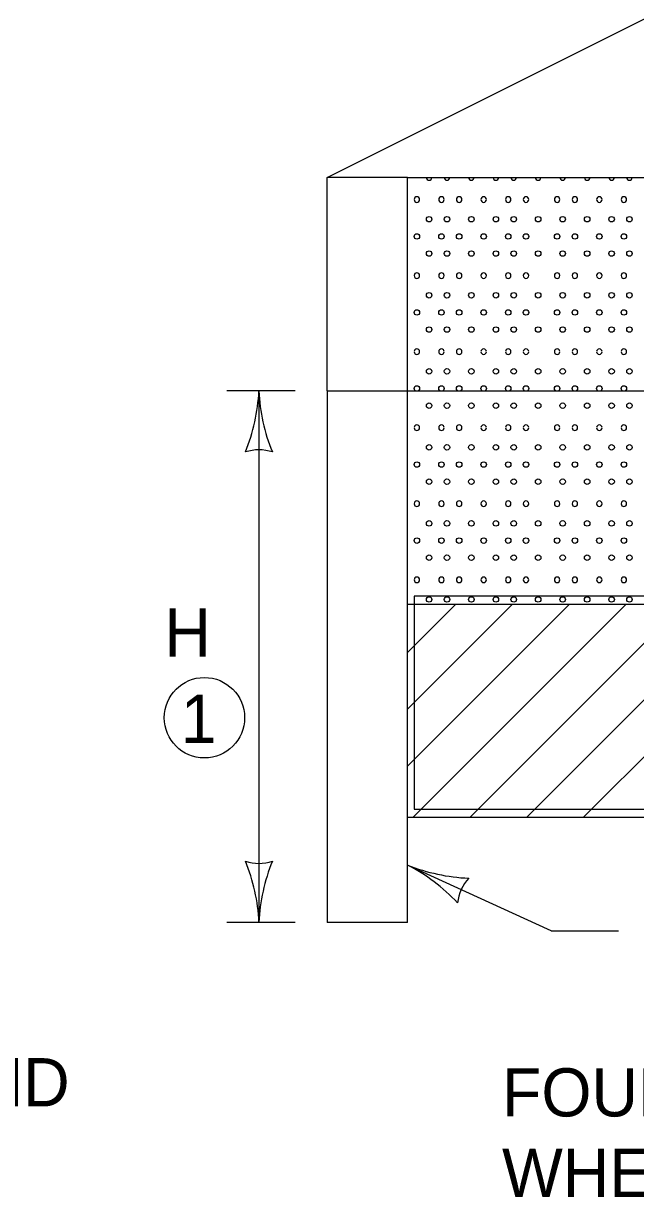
# Model space of a CAD drawing. Extents: x 49991.4 to 50021, y 49987.6 to 50011.4.
# Drawn here: x 50016.641 to 50017.403, y 50005.816 to 50007.277 of the extents above; entities that cross this region are included whole.
import ezdxf

# ---------------------------------------------------------------- set-up
doc = ezdxf.new("R2010")
doc.units = 0
for name, color, linetype in [('Level 1', 7, 'Continuous'), ('Level 2', 7, 'Continuous'), ('Level 3', 7, 'Continuous')]:
    doc.layers.add(name, color=color, linetype=linetype)

msp = doc.modelspace()

# ---------------------------------------------------------------- linework, layer by layer
at = {"layer": 'Level 1'}
for p, q in [((50017.0193, 50007.085), (50018.0803, 50007.6155)), ((50017.0193, 50006.8198), (50017.0193, 50007.085)), ((50017.1193, 50007.085), (50017.0193, 50007.085)), ((50017.1193, 50007.085), (50020.4675, 50007.085)), ((50017.1193, 50006.5545), (50017.1193, 50007.085)), ((50017.0193, 50006.8198), (50020.4675, 50006.8198)), ((50017.0193, 50006.8198), (50017.0193, 50006.1585)), ((50017.1193, 50006.5545), (50020.4675, 50006.5545)), ((50017.1193, 50006.1585), (50017.1193, 50006.5545)), ((50017.1193, 50006.4944), (50017.1794, 50006.5545)), ((50017.1193, 50006.4237), (50017.2501, 50006.5545)), ((50017.1193, 50006.353), (50017.3209, 50006.5545)), ((50017.1264, 50006.2893), (50017.3916, 50006.5545)), ((50020.4675, 50006.5645), (50017.1276, 50006.5644)), ((50017.1276, 50006.5644), (50017.1276, 50006.2993)), ((50017.1971, 50006.2893), (50017.4623, 50006.5545)), ((50017.2678, 50006.2893), (50017.533, 50006.5545)), ((50017.3385, 50006.2893), (50017.6037, 50006.5545)), ((50017.1193, 50006.2893), (50020.4675, 50006.2893)), ((50017.1276, 50006.2993), (50020.4675, 50006.2993)), ((50017.1193, 50006.1585), (50017.0193, 50006.1585))]:
    msp.add_line(p, q, dxfattribs=at)
for centre in [(50017.1462, 50007.0332), (50017.1684, 50007.0332), (50017.1988, 50007.0332), (50017.2293, 50007.0332), (50017.2515, 50007.0332), (50017.2819, 50007.0332), (50017.3124, 50007.0332), (50017.3429, 50007.0332), (50017.3733, 50007.0332), (50017.3955, 50007.0332), (50017.131, 50007.0118), (50017.131, 50007.0118), (50017.1615, 50007.0118), (50017.1836, 50007.0118), (50017.2141, 50007.0118), (50017.2141, 50007.0118), (50017.2446, 50007.0118), (50017.2667, 50007.0118), (50017.3055, 50007.0118), (50017.3276, 50007.0118), (50017.3581, 50007.0118), (50017.3581, 50007.0118), (50017.3886, 50007.0118), (50017.1462, 50006.9905), (50017.1684, 50006.9905), (50017.1988, 50006.9905), (50017.2293, 50006.9905), (50017.2515, 50006.9905), (50017.2819, 50006.9905), (50017.3124, 50006.9905), (50017.3429, 50006.9905), (50017.3733, 50006.9905), (50017.3955, 50006.9905), (50017.1462, 50006.9386), (50017.1684, 50006.9386), (50017.1988, 50006.9386), (50017.2293, 50006.9386), (50017.2515, 50006.9386), (50017.2819, 50006.9386), (50017.3124, 50006.9386), (50017.3429, 50006.9386), (50017.3733, 50006.9386), (50017.3955, 50006.9386), (50017.131, 50006.9172), (50017.131, 50006.9172), (50017.1615, 50006.9172), (50017.1836, 50006.9172), (50017.2141, 50006.9172), (50017.2141, 50006.9172), (50017.2446, 50006.9172), (50017.2667, 50006.9172), (50017.3055, 50006.9172), (50017.3276, 50006.9172), (50017.3581, 50006.9172), (50017.3581, 50006.9172), (50017.3886, 50006.9172), (50017.1462, 50006.8959), (50017.1684, 50006.8959), (50017.1988, 50006.8959), (50017.2293, 50006.8959), (50017.2515, 50006.8959), (50017.2819, 50006.8959), (50017.3124, 50006.8959), (50017.3429, 50006.8959), (50017.3733, 50006.8959), (50017.3955, 50006.8959), (50017.1462, 50006.844), (50017.1684, 50006.844), (50017.1988, 50006.844), (50017.2293, 50006.844), (50017.2515, 50006.844), (50017.2819, 50006.844), (50017.3124, 50006.844), (50017.3429, 50006.844), (50017.3733, 50006.844), (50017.3955, 50006.844), (50017.131, 50006.8226), (50017.131, 50006.8226), (50017.1615, 50006.8226), (50017.1836, 50006.8226), (50017.2141, 50006.8226), (50017.2141, 50006.8226), (50017.2446, 50006.8226), (50017.2667, 50006.8226), (50017.3055, 50006.8226), (50017.3276, 50006.8226), (50017.3581, 50006.8226), (50017.3581, 50006.8226), (50017.3886, 50006.8226), (50017.1462, 50006.8013), (50017.1684, 50006.8013), (50017.1988, 50006.8013), (50017.2293, 50006.8013), (50017.2515, 50006.8013), (50017.2819, 50006.8013), (50017.3124, 50006.8013), (50017.3429, 50006.8013), (50017.3733, 50006.8013), (50017.3955, 50006.8013), (50017.1462, 50006.7494), (50017.1684, 50006.7494), (50017.1988, 50006.7494), (50017.2293, 50006.7494), (50017.2515, 50006.7494), (50017.2819, 50006.7494), (50017.3124, 50006.7494), (50017.3429, 50006.7494), (50017.3733, 50006.7494), (50017.3955, 50006.7494), (50017.131, 50006.728), (50017.131, 50006.728), (50017.1615, 50006.728), (50017.1836, 50006.728), (50017.2141, 50006.728), (50017.2141, 50006.728), (50017.2446, 50006.728), (50017.2667, 50006.728), (50017.3055, 50006.728), (50017.3276, 50006.728), (50017.3581, 50006.728), (50017.3581, 50006.728), (50017.3886, 50006.728), (50017.1462, 50006.7067), (50017.1684, 50006.7067), (50017.1988, 50006.7067), (50017.2293, 50006.7067), (50017.2515, 50006.7067), (50017.2819, 50006.7067), (50017.3124, 50006.7067), (50017.3429, 50006.7067), (50017.3733, 50006.7067), (50017.3955, 50006.7067), (50017.1462, 50006.6548), (50017.1684, 50006.6548), (50017.1988, 50006.6548), (50017.2293, 50006.6548), (50017.2515, 50006.6548), (50017.2819, 50006.6548), (50017.3124, 50006.6548), (50017.3429, 50006.6548), (50017.3733, 50006.6548), (50017.3955, 50006.6548), (50017.131, 50006.6334), (50017.131, 50006.6334), (50017.1615, 50006.6334), (50017.1836, 50006.6334), (50017.2141, 50006.6334), (50017.2141, 50006.6334), (50017.2446, 50006.6334), (50017.2667, 50006.6334), (50017.3055, 50006.6334), (50017.3276, 50006.6334), (50017.3581, 50006.6334), (50017.3581, 50006.6334), (50017.3886, 50006.6334), (50017.1462, 50006.6121), (50017.1684, 50006.6121), (50017.1988, 50006.6121), (50017.2293, 50006.6121), (50017.2515, 50006.6121), (50017.2819, 50006.6121), (50017.3124, 50006.6121), (50017.3429, 50006.6121), (50017.3733, 50006.6121), (50017.3955, 50006.6121), (50017.1462, 50006.5602), (50017.1684, 50006.5602), (50017.1988, 50006.5602), (50017.2293, 50006.5602), (50017.2515, 50006.5602), (50017.2819, 50006.5602), (50017.3124, 50006.5602), (50017.3429, 50006.5602), (50017.3733, 50006.5602), (50017.3955, 50006.5602)]:
    msp.add_circle(centre, 0.00341, dxfattribs=at)
for centre, start, end in [((50017.1462, 50007.0851), 181.8336, 358.1664), ((50017.1684, 50007.0851), 181.8336, 358.1664), ((50017.1988, 50007.0851), 181.8336, 358.1664), ((50017.2293, 50007.0851), 181.8336, 358.1664), ((50017.2515, 50007.0851), 181.8336, 358.1664), ((50017.2819, 50007.0851), 181.8336, 358.1664), ((50017.3124, 50007.0851), 181.8336, 358.1664), ((50017.3429, 50007.0851), 181.8336, 358.1664), ((50017.3733, 50007.0851), 181.8336, 358.1664), ((50017.3955, 50007.0851), 181.8336, 358.1664), ((50017.131, 50007.0577), 0, 180), ((50017.131, 50007.0576), 180, 0), ((50017.131, 50007.0576), 180, 0), ((50017.1615, 50007.0577), 0, 180), ((50017.1615, 50007.0576), 180, 0), ((50017.1836, 50007.0577), 0, 180), ((50017.1836, 50007.0576), 180, 0), ((50017.2141, 50007.0577), 0, 180), ((50017.2141, 50007.0576), 180, 0), ((50017.2141, 50007.0576), 180, 0), ((50017.2446, 50007.0577), 0, 180), ((50017.2446, 50007.0576), 180, 0), ((50017.2667, 50007.0577), 0, 180), ((50017.2667, 50007.0576), 180, 0), ((50017.3055, 50007.0577), 0, 180), ((50017.3055, 50007.0576), 180, 0), ((50017.3276, 50007.0577), 0, 180), ((50017.3276, 50007.0576), 180, 0), ((50017.3581, 50007.0577), 0, 180), ((50017.3581, 50007.0576), 180, 0), ((50017.3581, 50007.0576), 180, 0), ((50017.3886, 50007.0577), 0, 180), ((50017.3886, 50007.0576), 180, 0), ((50017.131, 50006.9631), 0, 180), ((50017.131, 50006.963), 180, 0), ((50017.131, 50006.963), 180, 0), ((50017.1615, 50006.9631), 0, 180), ((50017.1615, 50006.963), 180, 0), ((50017.1836, 50006.9631), 0, 180), ((50017.1836, 50006.963), 180, 0), ((50017.2141, 50006.9631), 0, 180), ((50017.2141, 50006.963), 180, 0), ((50017.2446, 50006.9631), 0, 180), ((50017.2446, 50006.963), 180, 0), ((50017.2667, 50006.9631), 0, 180), ((50017.2667, 50006.963), 180, 0), ((50017.3055, 50006.9631), 0, 180), ((50017.3055, 50006.963), 180, 0), ((50017.3276, 50006.9631), 0, 180), ((50017.3276, 50006.963), 180, 0), ((50017.3581, 50006.9631), 0, 180), ((50017.3581, 50006.963), 180, 0), ((50017.3581, 50006.963), 180, 0), ((50017.3886, 50006.9631), 0, 180), ((50017.3886, 50006.963), 180, 0), ((50017.131, 50006.8685), 0, 180), ((50017.1615, 50006.8685), 0, 180), ((50017.1836, 50006.8685), 0, 180), ((50017.2141, 50006.8685), 0, 180), ((50017.2446, 50006.8685), 0, 180), ((50017.2667, 50006.8685), 0, 180), ((50017.3055, 50006.8685), 0, 180), ((50017.3276, 50006.8685), 0, 180), ((50017.3581, 50006.8685), 0, 180), ((50017.3886, 50006.8685), 0, 180), ((50017.131, 50006.8684), 180, 0), ((50017.131, 50006.8684), 180, 0), ((50017.1615, 50006.8684), 180, 0), ((50017.1836, 50006.8684), 180, 0), ((50017.2141, 50006.8684), 180, 0), ((50017.2141, 50006.8684), 180, 0), ((50017.2446, 50006.8684), 180, 0), ((50017.2667, 50006.8684), 180, 0), ((50017.3055, 50006.8684), 180, 0), ((50017.3276, 50006.8684), 180, 0), ((50017.3581, 50006.8684), 180, 0), ((50017.3581, 50006.8684), 180, 0), ((50017.3886, 50006.8684), 180, 0), ((50017.131, 50006.7739), 0, 180), ((50017.131, 50006.7738), 180, 0), ((50017.131, 50006.7738), 180, 0), ((50017.1615, 50006.7739), 0, 180), ((50017.1615, 50006.7738), 180, 0), ((50017.1836, 50006.7739), 0, 180), ((50017.1836, 50006.7738), 180, 0), ((50017.2141, 50006.7739), 0, 180), ((50017.2141, 50006.7738), 180, 0), ((50017.2141, 50006.7738), 180, 0), ((50017.2446, 50006.7739), 0, 180), ((50017.2446, 50006.7738), 180, 0), ((50017.2667, 50006.7739), 0, 180), ((50017.2667, 50006.7738), 180, 0), ((50017.3055, 50006.7739), 0, 180), ((50017.3055, 50006.7738), 180, 0), ((50017.3276, 50006.7739), 0, 180), ((50017.3276, 50006.7738), 180, 0), ((50017.3581, 50006.7739), 0, 180), ((50017.3581, 50006.7738), 180, 0), ((50017.3581, 50006.7738), 180, 0), ((50017.3886, 50006.7739), 0, 180), ((50017.3886, 50006.7738), 180, 0), ((50017.131, 50006.6793), 0, 180), ((50017.1615, 50006.6793), 0, 180), ((50017.1836, 50006.6793), 0, 180), ((50017.2141, 50006.6793), 0, 180), ((50017.2446, 50006.6793), 0, 180), ((50017.2667, 50006.6793), 0, 180), ((50017.3055, 50006.6793), 0, 180), ((50017.3276, 50006.6793), 0, 180), ((50017.3581, 50006.6793), 0, 180), ((50017.3886, 50006.6793), 0, 180), ((50017.131, 50006.6792), 180, 0), ((50017.131, 50006.6792), 180, 0), ((50017.1615, 50006.6792), 180, 0), ((50017.1836, 50006.6792), 180, 0), ((50017.2141, 50006.6792), 180, 0), ((50017.2141, 50006.6792), 180, 0), ((50017.2446, 50006.6792), 180, 0), ((50017.2667, 50006.6792), 180, 0), ((50017.3055, 50006.6792), 180, 0), ((50017.3276, 50006.6792), 180, 0), ((50017.3581, 50006.6792), 180, 0), ((50017.3581, 50006.6792), 180, 0), ((50017.3886, 50006.6792), 180, 0), ((50017.131, 50006.5847), 0, 180), ((50017.131, 50006.5846), 180, 0), ((50017.131, 50006.5846), 180, 0), ((50017.1615, 50006.5847), 0, 180), ((50017.1615, 50006.5846), 180, 0), ((50017.1836, 50006.5847), 0, 180), ((50017.1836, 50006.5846), 180, 0), ((50017.2141, 50006.5847), 0, 180), ((50017.2141, 50006.5846), 180, 0), ((50017.2141, 50006.5846), 180, 0), ((50017.2446, 50006.5847), 0, 180), ((50017.2446, 50006.5846), 180, 0), ((50017.2667, 50006.5847), 0, 180), ((50017.2667, 50006.5846), 180, 0), ((50017.3055, 50006.5847), 0, 180), ((50017.3055, 50006.5846), 180, 0), ((50017.3276, 50006.5847), 0, 180), ((50017.3276, 50006.5846), 180, 0), ((50017.3581, 50006.5847), 0, 180), ((50017.3581, 50006.5846), 180, 0), ((50017.3581, 50006.5846), 180, 0), ((50017.3886, 50006.5847), 0, 180), ((50017.3886, 50006.5846), 180, 0)]:
    msp.add_arc(centre, 0.00341, start, end, dxfattribs=at)
at = {"layer": 'Level 2'}
msp.add_circle((50016.8665, 50006.4131), 0.05, dxfattribs=at)
at = {"layer": 'Level 3'}
for p, q in [((50016.9793, 50006.8198), (50016.8943, 50006.8198)), ((50016.9343, 50006.8198), (50016.9343, 50006.1585)), ((50017.0193, 50006.7798), (50017.0193, 50006.5048)), ((50017.298, 50006.148), (50017.1193, 50006.2298)), ((50016.9793, 50006.1585), (50016.8943, 50006.1585)), ((50017.298, 50006.148), (50017.382, 50006.148))]:
    msp.add_line(p, q, dxfattribs=at)
for centre, radius, start, end in [((50016.7016, 50006.8312), 0.233, 337.9228, 357.1727), ((50017.1564, 50006.8289), 0.2223, 182.3605, 202.544), ((50016.9343, 50006.6915), 0.0548, 72.1388, 107.8612), ((50016.7122, 50006.1494), 0.2223, 2.3605, 22.544), ((50016.9343, 50006.2867), 0.0548, 252.1388, 287.8612), ((50017.167, 50006.147), 0.233, 157.9228, 177.1727), ((50017.0185, 50006.0316), 0.2223, 42.8606, 63.0441), ((50017.2057, 50006.4462), 0.233, 248.2319, 267.4817), ((50017.2359, 50006.1764), 0.0548, 137.5434, 173.2657)]:
    msp.add_arc(centre, radius, start, end, dxfattribs=at)

# ---------------------------------------------------------------- texts
at = {"layer": 'Level 2'}
for s, p in [('H', (50016.8168, 50006.4891)), ('1', (50016.8369, 50006.3818)), ('EXISTING GROUND', (50015.9454, 50005.9296)), ('FOUNDATION MATERIAL ', (50017.2369, 50005.917)), ('WHEN SPECIFIED', (50017.2369, 50005.817))]:
    msp.add_text(s, height=0.06, dxfattribs=at).set_placement(p)

doc.saveas('drawing.dxf')
